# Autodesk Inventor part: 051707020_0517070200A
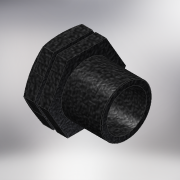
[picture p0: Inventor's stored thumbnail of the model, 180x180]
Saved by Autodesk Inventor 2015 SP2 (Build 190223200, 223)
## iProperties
Created: 2017-05
Part Number: 051707020_0517070200A
Material: Generic
Description: PLASSON PLUG 2"
Document SubType Name: Modeling
Designer: Кирилл
Density: 1 g/cm^3
Appearance: Black Cast
Author: Кирилл
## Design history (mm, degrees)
derived "051707.ipt"
feature "Solid1::051707.ipt"
tag "TaggingFeature1"
body "Solid1"
other parameters: "d1" = 59.614, "d2" = 65, "d5" = 25, "d6" = 6.42857, "d8" = 0.45, "d12" = 0, "d14" = 2.14286, "d15" = 45, "d16" = 2.57143, "d17" = 6.42857, "d19" = 0, "d21" = 3.3, "d29" = 0, "H_" = 45, "R_" = 59.614, "E_" = 65, "l_2" = 25, "d20" = 5
